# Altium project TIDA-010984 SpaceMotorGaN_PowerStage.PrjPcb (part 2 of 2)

## Sheet TIDA-010984 PowerSupply.SchDoc
size 431 x 279 mm; Date: Not shown in title block; ApprovedBy: Not shown in title block; CheckedBy: Not shown in title block; Author: Not shown in title block; CompanyName: Not shown in title block; Engineer: Not shown in title block; Organization: Not shown in title block; Address1: Not shown in title block; Address2: Not shown in title block; Address3: Not shown in title block; Address4: Not shown in title block; DocumentNumber: 2; Revision: Use project parameter SCH_Rev; SheetNumber: 3; SheetTotal: 6; PageSetup: Record=PageOptions¦CenterHorizontal=True¦CenterVertical=True¦PrintScale=1.00¦XCorrection=1.00¦YCorrection=1.00¦PrintKind=0¦BorderSize=5000000¦LeftOffset=0¦BottomOffset=0¦Orientation=2¦PaperLength=1000¦PaperWidth=1000¦Scale=100¦PaperSource=15¦PrintQuality=600¦MediaType=1¦DitherType=10¦PaperKind=Letter¦PrintScaleMode=1
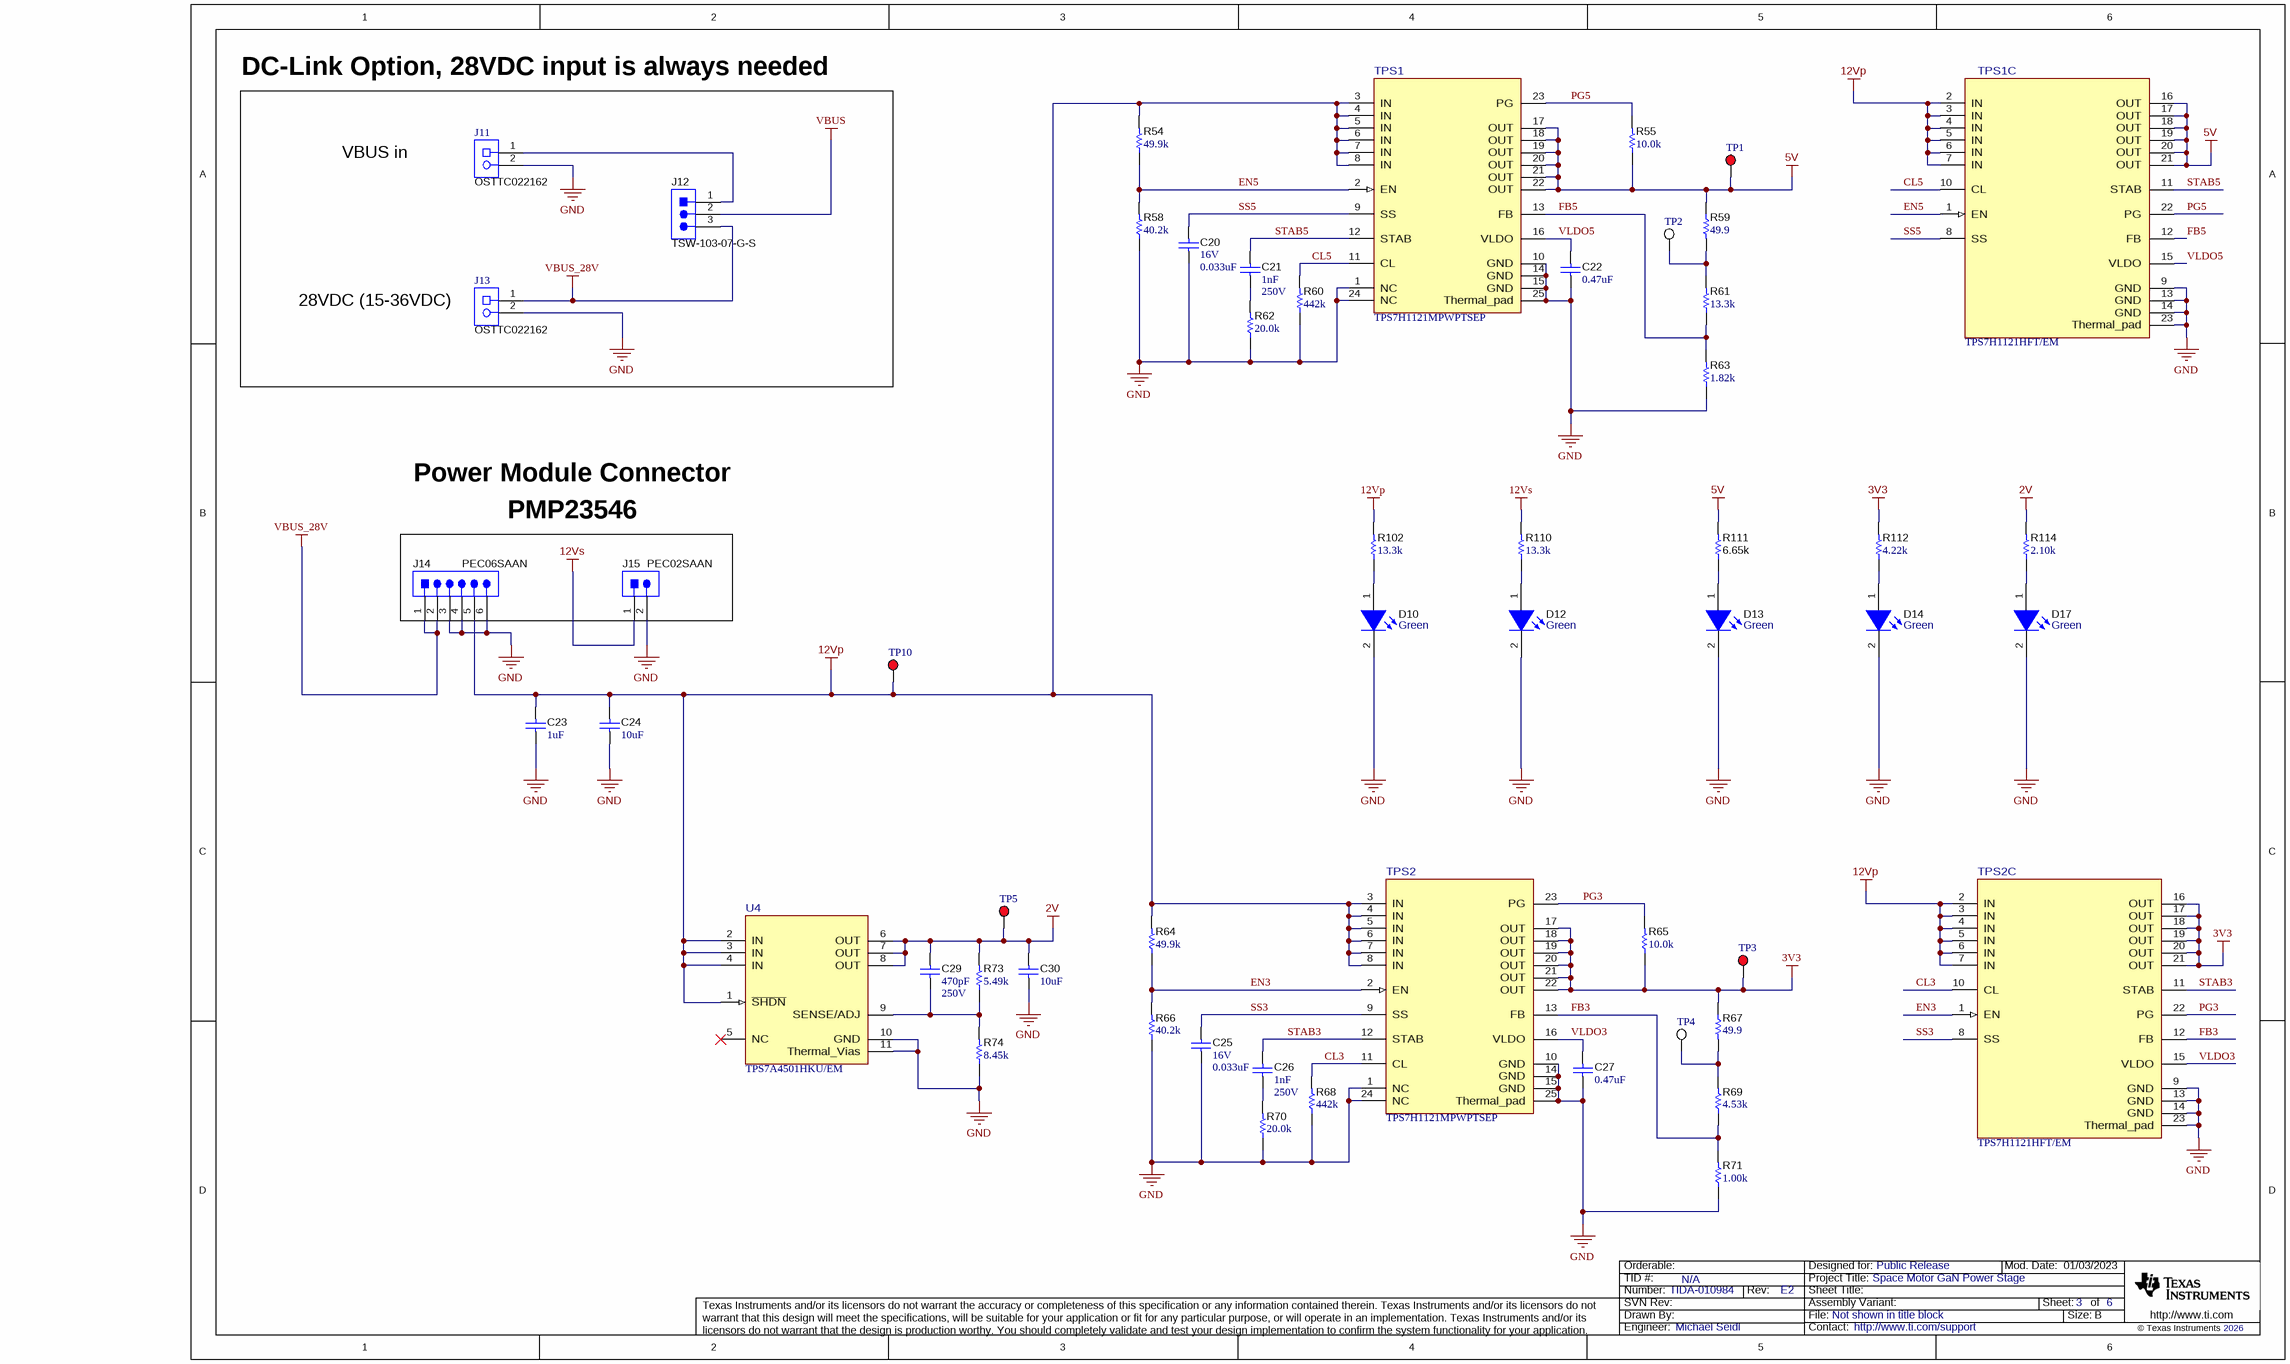
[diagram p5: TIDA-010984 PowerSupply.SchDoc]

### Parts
C20  VDC_V: 16V  ValueDisplayed: 0.033uF  [0603]  (hidden comment: GRM188R71C333KA01D)
C21  Cap_F: 1nF  VDC_V: 250V  [0603]  (hidden comment: GRM188R72E102KW07D)
C22  ValueDisplayed: 0.47uF  [0603]  (hidden comment: GRM188R71E474KA12D)
C23  ValueDisplayed: 1uF  [1210_150]  (hidden comment: 12103C105KAT2A)
C24  ValueDisplayed: 10uF  [1210_280]  (hidden comment: C1210C106K3RACTU)
C25  VDC_V: 16V  ValueDisplayed: 0.033uF  [0603]  (hidden comment: GRM188R71C333KA01D)
C26  Cap_F: 1nF  VDC_V: 250V  [0603]  (hidden comment: GRM188R72E102KW07D)
C27  ValueDisplayed: 0.47uF  [0603]  (hidden comment: GRM188R71E474KA12D)
C29  Cap_F: 470pF  VDC_V: 250V  [0603]  (hidden comment: GRM188R72E471KW07D)
C30  ValueDisplayed: 10uF  [1210_280]  (hidden comment: C1210C106K3RACTU)
D10  value Green  [APT2012_Green]  (hidden comment: APT2012LZGCK)
D12  value Green  [APT2012_Green]  (hidden comment: APT2012LZGCK)
D13  value Green  [APT2012_Green]  (hidden comment: APT2012LZGCK)
D14  value Green  [APT2012_Green]  (hidden comment: APT2012LZGCK)
D17  value Green  [APT2012_Green]  (hidden comment: APT2012LZGCK)
J11  OSTTC022162  [On-Shore_OSTTC022162]
J12  TSW-103-07-G-S  [TSW-103-07-G-S]
J13  OSTTC022162  [On-Shore_OSTTC022162]
J14  PEC06SAAN  [Sullins_PEC06SAAN]
J15  PEC02SAAN  [CONN_PEC02SAAN]
R54  ValueDisplayed: 49.9k  [0603]  (hidden comment: CRCW060349K9FKEA)
R55  ValueDisplayed: 10.0k  [0603]  (hidden comment: RC0603FR-0710KL)
R58  ValueDisplayed: 40.2k  [0603]  (hidden comment: CRCW060340K2FKEA)
R59  ValueDisplayed: 49.9  [0603]  (hidden comment: CRCW060349R9FKEA)
R60  ValueDisplayed: 442k  [0603]  (hidden comment: CRCW0603442KFKEA)
R61  ValueDisplayed: 13.3k  [0603]  (hidden comment: CRCW060313K3FKEA)
R62  ValueDisplayed: 20.0k  [0603]  (hidden comment: CRCW060320K0FKEA)
R63  ValueDisplayed: 1.82k  [0603]  (hidden comment: CRCW06031K82FKEA)
R64  ValueDisplayed: 49.9k  [0603]  (hidden comment: CRCW060349K9FKEA)
R65  ValueDisplayed: 10.0k  [0603]  (hidden comment: RC0603FR-0710KL)
R66  ValueDisplayed: 40.2k  [0603]  (hidden comment: CRCW060340K2FKEA)
R67  ValueDisplayed: 49.9  [0603]  (hidden comment: CRCW060349R9FKEA)
R68  ValueDisplayed: 442k  [0603]  (hidden comment: CRCW0603442KFKEA)
R69  ValueDisplayed: 4.53k  [0603]  (hidden comment: CRCW06034K53FKEA)
R70  ValueDisplayed: 20.0k  [0603]  (hidden comment: CRCW060320K0FKEA)
R71  ValueDisplayed: 1.00k  [0603]  (hidden comment: CRCW06031K00FKEA)
R73  ValueDisplayed: 5.49k  [0603]  (hidden comment: CRCW06035K49FKEA)
R74  ValueDisplayed: 8.45k  [0603]  (hidden comment: CRCW06038K45FKEA)
R102  ValueDisplayed: 13.3k  [0603]  (hidden comment: CRCW060313K3FKEA)
R110  ValueDisplayed: 13.3k  [0603]  (hidden comment: CRCW060313K3FKEA)
R111  ValueDisplayed: 6.65k  [0603]  (hidden comment: RC0603FR-076K65L)
R112  ValueDisplayed: 4.22k  [0603]  (hidden comment: RC0603FR-074K22L)
R114  ValueDisplayed: 2.10k  [0603]  (hidden comment: RC0603FR-072K1L)
TP1  5010  [Keystone5010]  (value not drawn)
TP2  5012  [Keystone5012]  (value not drawn)
TP3  5010  [Keystone5010]  (value not drawn)
TP4  5012  [Keystone5012]  (value not drawn)
TP5  5010  [Keystone5010]  (value not drawn)
TP10  5010  [Keystone5010]  (value not drawn)
TPS1  TPS7H1121MPWPTSEP  [PWP0024R-MFG]
TPS1C  TPS7H1121HFT/EM  [HFT0022A-C01-MFG]
TPS2  TPS7H1121MPWPTSEP  [PWP0024R-MFG]
TPS2C  TPS7H1121HFT/EM  [HFT0022A-C01-MFG]
U4  TPS7A4501HKU/EM  [HKU0010A-IPC_B]

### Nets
2V: C29.1 C30.1 R73.2 R114.2 TP5.1 U4.6(OUT) U4.7(OUT) U4.8(OUT)
3V3: R65.1 R67.1 R112.2 TP3.1 TPS2.17(OUT) TPS2.18(OUT) TPS2.19(OUT) TPS2.20(OUT) TPS2.21(OUT) TPS2.22(OUT) TPS2C.16(OUT) TPS2C.17(OUT) TPS2C.18(OUT) TPS2C.19(OUT) TPS2C.20(OUT) TPS2C.21(OUT)
5V: R55.1 R59.1 R111.2 TP1.1 TPS1.17(OUT) TPS1.18(OUT) TPS1.19(OUT) TPS1.20(OUT) TPS1.21(OUT) TPS1.22(OUT) TPS1C.16(OUT) TPS1C.17(OUT) TPS1C.18(OUT) TPS1C.19(OUT) TPS1C.20(OUT) TPS1C.21(OUT)
12Vp: C23.1 C24.1 J14.5 R54.2 R64.2 R102.2 TP10.1 TPS1.3(IN) TPS1.4(IN) TPS1.5(IN) TPS1.6(IN) TPS1.7(IN) TPS1.8(IN) TPS1C.2(IN) TPS1C.3(IN) TPS1C.4(IN) TPS1C.5(IN) TPS1C.6(IN) TPS1C.7(IN) TPS2.3(IN) TPS2.4(IN) TPS2.5(IN) TPS2.6(IN) TPS2.7(IN) TPS2.8(IN) TPS2C.2(IN) TPS2C.3(IN) TPS2C.4(IN) TPS2C.5(IN) TPS2C.6(IN) TPS2C.7(IN) U4.1(~{SHDN}) U4.2(IN) U4.3(IN) U4.4(IN)
12Vs: J15.1 R110.2
GND: C20.2 C22.2 C23.2 C24.2 C25.2 C27.2 C30.2 D10.2(K) D12.2(K) D13.2(K) D14.2(K) D17.2(K) J11.2 J13.2 J14.3 J14.4 J14.6 J15.2 R58.1 R60.1 R62.1 R63.1 R66.1 R68.1 R70.1 R71.1 R74.1 TPS1.1(NC) TPS1.10(GND) TPS1.14(GND) TPS1.15(GND) TPS1.24(NC) TPS1.25(Thermal_pad) TPS1C.9(GND) TPS1C.13(GND) TPS1C.14(GND) TPS1C.23(Thermal_pad) TPS2.1(NC) TPS2.10(GND) TPS2.14(GND) TPS2.15(GND) TPS2.24(NC) TPS2.25(Thermal_pad) TPS2C.9(GND) TPS2C.13(GND) TPS2C.14(GND) TPS2C.23(Thermal_pad) U4.10(GND) U4.11(Thermal_Vias)
VBUS: J12.2
VBUS_28V: J12.3 J13.1 J14.1 J14.2
CL3: R68.2 TPS2.11(CL) TPS2C.10(CL)
CL5: R60.2 TPS1.11(CL) TPS1C.10(CL)
EN3: R64.1 R66.2 TPS2.2(EN) TPS2C.1(EN)
EN5: R54.1 R58.2 TPS1.2(EN) TPS1C.1(EN)
FB3: R69.1 R71.2 TPS2.13(FB) TPS2C.12(FB)
FB5: R61.1 R63.2 TPS1.13(FB) TPS1C.12(FB)
PG3: R65.2 TPS2.23(PG) TPS2C.22(PG)
PG5: R55.2 TPS1.23(PG) TPS1C.22(PG)
SS3: C25.1 TPS2.9(SS) TPS2C.8(SS)
SS5: C20.1 TPS1.9(SS) TPS1C.8(SS)
STAB3: C26.1 TPS2.12(STAB) TPS2C.11(STAB)
STAB5: C21.1 TPS1.12(STAB) TPS1C.11(STAB)
VLDO3: C27.1 TPS2.16(VLDO) TPS2C.15(VLDO)
VLDO5: C22.1 TPS1.16(VLDO) TPS1C.15(VLDO)
NetC21_2: C21.2 R62.2
NetC26_2: C26.2 R70.2
NetC29_2: C29.2 R73.1 R74.2 U4.9(SENSE/ADJ)
NetD10_1: D10.1(A) R102.1
NetD12_1: D12.1(A) R110.1
NetD13_1: D13.1(A) R111.1
NetD14_1: D14.1(A) R112.1
NetD17_1: D17.1(A) R114.1
NetJ11_1: J11.1 J12.1
NetR59_2: R59.2 R61.2 TP2.1
NetR67_2: R67.2 R69.2 TP4.1

Not connected (* = marked no-connect by the designer): U4 5(NC)*

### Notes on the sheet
- DC-Link Option, 28VDC input is always needed
- VBUS in
- 28VDC (15-36VDC)
- Power Module Connector
- PMP23546

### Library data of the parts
C20 C25 = CMP-0007392-5: CAP, CERM, 0.033 uF, 16 V, +/- 10%, X7R, 0603; Manufacturer: MuRata; TaMin_C: -55°C; Polarized: N; SizeAreaWB_mm2: 4.68; Value1: Unknown; U/M: EA; TaMax_C: 125°C; SizeZ_mm: 1; SizeX_mm: 1.6; SizeY_mm: 0.8; SizeArea_mm2: 1.28; Cap_F: 33nF; AEC Category: Q200
C21 C26 = CMP-0007490-4: CAP, CERM, 1000 pF, 250 V, +/- 10%, X7R, 0603; Manufacturer: MuRata; TaMin_C: -55°C; Polarized: N; SizeAreaWB_mm2: 4.68; Value1: Unknown; U/M: EA; Value: 1000pF; TaMax_C: 125°C; SizeZ_mm: 1; SizeX_mm: 1.6; SizeY_mm: 0.8; SizeArea_mm2: 1.28; AEC Category: Q200
C22 C27 = CMP-0007424-4: CAP, CERM, 0.47 uF, 25 V, +/- 10%, X7R, 0603; Manufacturer: MuRata; TaMin_C: -55°C; Polarized: N; SizeAreaWB_mm2: 4.68; Value1: Unknown; U/M: EA; Value: 0.47uF; TaMax_C: 125°C; SizeZ_mm: 1; SizeX_mm: 1.6; SizeY_mm: 0.8; Value2: 25V; SizeArea_mm2: 1.28; Cap_F: 470nF; AEC Category: Q200
C23 = CMP-0009061-1: CAP, CERM, 1 uF, 25 V, +/- 10%, X7R, 1210; Manufacturer: AVX; TaMin_C: -55°C; Polarized: N; SizeAreaWB_mm2: 14.7; Value1: Unknown; U/M: EA; Value: 1uF; TaMax_C: 125°C; SizeZ_mm: 1.5; SizeX_mm: 3.2; SizeY_mm: 2.5; Cap_Case: 1210; Value2: 25V; SizeArea_mm2: 8; Cap_F: 1µF; AEC Category: Q200
C24 C30 = CMP-0009078-1: CAP, CERM, 10 uF, 25 V, +/- 10%, X7R, 1210; Manufacturer: Kemet; TaMin_C: -55°C; Polarized: N; SizeAreaWB_mm2: 14.7; Value1: Unknown; U/M: EA; Value: 10uF; TaMax_C: 125°C; SizeZ_mm: 2.8; SizeX_mm: 3.2; SizeY_mm: 2.5; Cap_Case: 1210; Value2: 25V; SizeArea_mm2: 8; Cap_F: 10µF; AEC Category: Q200
C29 = CMP-0007495-4: CAP, CERM, 470 pF, 250 V, +/- 10%, X7R, 0603; Manufacturer: MuRata; TaMin_C: -55°C; Polarized: N; SizeAreaWB_mm2: 4.68; Value1: Unknown; U/M: EA; Value: 470pF; TaMax_C: 125°C; SizeZ_mm: 1; SizeX_mm: 1.6; SizeY_mm: 0.8; SizeArea_mm2: 1.28; AEC Category: Q200
D10 D12-D14 D17 = CMP-0002953-3: LED, Green, SMD; Manufacturer: Kingbright; Vr_V: 5V; Value2: 2.65V; Ir_A: 50µA; Angle: 120; Tjmax_C: 85°C; Type: InGaN; Power_TotalModule: 75mW; Io_A: 2mA; Value1: 0.075W
J11 J13 = CMP-0075044-1: Terminal Block, 2-pole, 200mil, TH; Manufacturer: On-Shore Technology; CNHeader: False; CT: True; Green_Lifecycle: Not Set; Green_REACh: Incomplete
J12 = CMP-0075407-2: Header, 100mil, 3x1, Gold, TH; Manufacturer: Samtec; Pitch_mm: 2.54; Cert_VDE: N; Gender: Male; Cert_CSA: Y; Voltage_V: 550V; Green_REACh: Passed; Current_A: 6.3A; Green_Lifecycle: Active; Row_Count: 1
J14 = CMP-0054567-1: Header, 100mil, 6x1, Tin, TH; Manufacturer: Sullins Connector Solutions; CNHeader: TRUE; Green_Lifecycle: Not Set; Green_REACh: Incomplete; CT: FALSE
J15 = CMP-0002337-1: Header, 100mil, 2x1, Tin, TH; Manufacturer: Sullins Connector Solutions; Pitch_mm: 2.54; Gender: Male; Shrouded: N; Row_Count: 1; Current_A: 3A; Voltage_V: 1.8kV; Cert_UL: Y; CNHeader: TRUE; CT: FALSE; Green_Lifecycle: Not Set; Green_REACh: Incomplete
R54 R64 = CMP-0022447-4: RES, 49.9 k, 1%, 0.1 W, AEC-Q200 Grade 0, 0603; Manufacturer: Vishay-Dale; Power_W: 100mW; TempCo: 100 ppm/C; Value_Code: 49k9; Value: 49.9k; EIA_Code: E96; SizeX_mm: 1.6; SizeY_mm: 0.8; SizeZ_mm: 1; Value2: 0.1W; SizeArea_mm2: 1.28; AEC Qualified: Y; VDC_V: 75V; AEC Category: Q200; AEC Grade: 0
R55 R65 = CMP-0022746-5: RES, 10.0 k, 1%, 0.1 W, 0603; Manufacturer: Yageo; Power_W: 100mW; TempCo: 100 ppm/C; Value_Code: 10k0; Value: 10.0k; EIA_Code: E96; Res_ohm: 10k; SizeX_mm: 1.6; SizeY_mm: 0.8; SizeZ_mm: 1; Value2: 0.1W; SizeArea_mm2: 1.28; AEC Qualified: N; VDC_V: 75V; AEC Category: Q200; SizeAreaWB_mm2: 4.68
R58 R66 = CMP-0022410-4: RES, 40.2 k, 1%, 0.1 W, AEC-Q200 Grade 0, 0603; Manufacturer: Vishay-Dale; Power_W: 100mW; TempCo: 100 ppm/C; Value_Code: 40k2; Value: 40.2k; EIA_Code: E96; SizeX_mm: 1.6; SizeY_mm: 0.8; SizeZ_mm: 1; Value2: 0.1W; SizeArea_mm2: 1.28; AEC Qualified: Y; VDC_V: 75V; AEC Category: Q200; AEC Grade: 0
R59 R67 = CMP-0022448-4: RES, 49.9, 1%, 0.1 W, AEC-Q200 Grade 0, 0603; Manufacturer: Vishay-Dale; Power_W: 100mW; SizeZ_mm: 1; SizeArea_mm2: 1.28; Value2: 0.1W; Value_Code: 49R9; Value: 49.9; AEC Qualified: Y; AEC Category: Q200; AEC Grade: 0; SizeX_mm: 1.6; TempCo: 100 ppm/C; EIA_Code: E96; VDC_V: 75V; SizeY_mm: 0.8
R60 R68 = CMP-0022424-4: RES, 442 k, 1%, 0.1 W, AEC-Q200 Grade 0, 0603; Manufacturer: Vishay-Dale; Power_W: 100mW; TempCo: 100 ppm/C; Value: 442k; EIA_Code: E96; SizeX_mm: 1.6; SizeY_mm: 0.8; SizeZ_mm: 1; Value2: 0.1W; SizeArea_mm2: 1.28; AEC Qualified: Y; VDC_V: 75V; AEC Category: Q200; AEC Grade: 0
R61 R102 R110 = CMP-0022043-4: RES, 13.3 k, 1%, 0.1 W, AEC-Q200 Grade 0, 0603; Manufacturer: Vishay-Dale; Power_W: 100mW; TempCo: 100 ppm/C; Value_Code: 13k3; Value: 13.3k; EIA_Code: E96; SizeX_mm: 1.6; SizeY_mm: 0.8; SizeZ_mm: 1; Value2: 0.1W; SizeArea_mm2: 1.28; AEC Qualified: Y; VDC_V: 75V; AEC Category: Q200; AEC Grade: 0
R62 R70 = CMP-0022204-4: RES, 20.0 k, 1%, 0.1 W, AEC-Q200 Grade 0, 0603; Manufacturer: Vishay-Dale; Power_W: 100mW; TempCo: 100 ppm/C; Value_Code: 20k0; Value: 20.0k; EIA_Code: E96; Res_ohm: 20k; SizeX_mm: 1.6; SizeY_mm: 0.8; SizeZ_mm: 1; Value2: 0.1W; SizeArea_mm2: 1.28; AEC Qualified: Y; VDC_V: 75V; AEC Category: Q200; AEC Grade: 0
R63 = CMP-0022134-4: RES, 1.82 k, 1%, 0.1 W, AEC-Q200 Grade 0, 0603; Manufacturer: Vishay-Dale; Power_W: 100mW; TempCo: 100 ppm/C; Value_Code: 1k82; Value: 1.82k; EIA_Code: E96; SizeX_mm: 1.6; SizeY_mm: 0.8; SizeZ_mm: 1; Value2: 0.1W; SizeArea_mm2: 1.28; AEC Qualified: Y; VDC_V: 75V; AEC Category: Q200; AEC Grade: 0
R69 = CMP-0022454-4: RES, 4.53 k, 1%, 0.1 W, AEC-Q200 Grade 0, 0603; Manufacturer: Vishay-Dale; Power_W: 100mW; TempCo: 100 ppm/C; Value_Code: 4k53; Value: 4.53k; EIA_Code: E96; SizeX_mm: 1.6; SizeY_mm: 0.8; SizeZ_mm: 1; Value2: 0.1W; SizeArea_mm2: 1.28; AEC Qualified: Y; VDC_V: 75V; AEC Category: Q200; AEC Grade: 0
R71 = CMP-0022109-5: RES, 1.00 k, 1%, 0.1 W, AEC-Q200 Grade 0, 0603; Manufacturer: Vishay-Dale; Power_W: 100mW; TempCo: 100 ppm/C; Value_Code: 1k00; Value: 1.00k; EIA_Code: E96; Res_ohm: 1k; SizeX_mm: 1.6; SizeY_mm: 0.8; SizeZ_mm: 1; Value2: 0.1W; SizeArea_mm2: 1.28; AEC Qualified: Y; VDC_V: 75V; AEC Category: Q200; AEC Grade: 0
R73 = CMP-0022512-4: RES, 5.49 k, 1%, 0.1 W, AEC-Q200 Grade 0, 0603; Manufacturer: Vishay-Dale; Power_W: 100mW; TempCo: 100 ppm/C; Value_Code: 5k49; Value: 5.49k; EIA_Code: E96; SizeX_mm: 1.6; SizeY_mm: 0.8; SizeZ_mm: 1; Value2: 0.1W; SizeArea_mm2: 1.28; AEC Qualified: Y; VDC_V: 75V; AEC Category: Q200; AEC Grade: 0
R74 = CMP-0022636-4: RES, 8.45 k, 1%, 0.1 W, AEC-Q200 Grade 0, 0603; Manufacturer: Vishay-Dale; Power_W: 100mW; TempCo: 100 ppm/C; Value_Code: 8k45; Value: 8.45k; EIA_Code: E96; SizeX_mm: 1.6; SizeY_mm: 0.8; SizeZ_mm: 1; Value2: 0.1W; SizeArea_mm2: 1.28; AEC Qualified: Y; VDC_V: 75V; AEC Category: Q200; AEC Grade: 0
R111 = CMP-0023251-5: RES, 6.65 k, 1%, 0.1 W, 0603; Manufacturer: Yageo; Power_W: 100mW; TempCo: 100 ppm/C; Value_Code: 6k65; Value: 6.65k; EIA_Code: E96; SizeX_mm: 1.6; SizeY_mm: 0.8; SizeZ_mm: 1; Value2: 0.1W; SizeArea_mm2: 1.28; AEC Qualified: N; VDC_V: 75V; AEC Category: Q200; SizeAreaWB_mm2: 4.68
R112 = CMP-0023146-5: RES, 4.22 k, 1%, 0.1 W, 0603; Manufacturer: Yageo; Power_W: 100mW; TempCo: 100 ppm/C; Value_Code: 4k22; Value: 4.22k; EIA_Code: E96; SizeX_mm: 1.6; SizeY_mm: 0.8; SizeZ_mm: 1; Value2: 0.1W; SizeArea_mm2: 1.28; AEC Qualified: N; VDC_V: 75V; AEC Category: Q200; SizeAreaWB_mm2: 4.68
R114 = CMP-0022983-5: RES, 2.10 k, 1%, 0.1 W, 0603; Manufacturer: Yageo; Power_W: 100mW; TempCo: 100 ppm/C; Value_Code: 2k10; Value: 2.10k; EIA_Code: E96; Res_ohm: 2.1k; SizeX_mm: 1.6; SizeY_mm: 0.8; SizeZ_mm: 1; Value2: 0.1W; SizeArea_mm2: 1.28; AEC Qualified: N; VDC_V: 75V; AEC Category: Q200; SizeAreaWB_mm2: 4.68
TP1 TP3 TP5 TP10 = CMP-0055147-2: Test Point, Multipurpose, Red, TH; Manufacturer: Keystone Electronics; CNHeader: FALSE; Green_Lifecycle: Active; Green_REACh: Passed; ContactFinish: Silver; CT: TRUE
TP2 TP4 = CMP-0055149-2: Test Point, Multipurpose, White, TH; Manufacturer: Keystone Electronics; CNHeader: FALSE; Green_Lifecycle: Active; Green_REACh: Passed; ContactFinish: Silver; CT: TRUE
TPS1 TPS2 = CMP-0122232-1: 2.25 V to 14-V Input, 2-A, Radiation Hardened LDO Regulator; Manufacturer: Texas Instruments; SizeZ_mm: 1.2mm; AEC Qualified: No; Accuracy Percentage: 1.5%; Dropout Voltage: 1000mV; Max Supply Voltage: 14V; Min Supply Voltage: 2.25V; Nominal Supply Current: 8-10mA; Number Of Outputs: 1; Output Type: AdjustableProgrammable; Output Voltage: 0.6-13.9V; Standoff Height: 0.05mm; TJmax_C: +125°C
TPS1C TPS2C = CMP-0032523-3: 2.25 V to 14-V Input, 2-A, Radiation Hardened LDO Regulator; Manufacturer: Texas Instruments; SizeZ_mm: 2.428mm; AEC Qualified: No; Accuracy Percentage: 1.1%; Dropout Voltage: 1000mV; Max Supply Voltage: 14V; Min Supply Voltage: 2.25V; Nominal Supply Current: 10mA; Number Of Outputs: 1; Output Type: AdjustableProgrammable; Output Voltage: 0.6-13.9V; Standoff Height: 0.555mm; TJmax_C: +125°C; AEC Category: Q200; CompType: IC
U4 = CMP-0097443-1: LDO Regulator Pos 1.21V to 20V 0.75A 10-Pin CFP Tube; Manufacturer: Texas Instruments; Nominal Supply Current: 1-28mA; Output Type: AdjustableProgrammable; Dropout Voltage: 0.2V; Standoff Height: 0mm; SizeZ_mm: 2.62mm; TJmax_C: +125°C; Number Of Outputs: 1; AEC Qualified: No; Min Supply Voltage: 2.9V; Output Voltage: 1.21-20V; Accuracy Percentage: 1.15%

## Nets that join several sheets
2V: TIDA-010984 TempSensing (C57.2 U8.12), TIDA-010984 PowerSupply (8 pins)
3V3: PA (5 pins), PB (5 pins), PC (5 pins), PE (5 pins), PD (5 pins), PF (5 pins), TIDA-010984 Interface (20 pins), TIDA-010984 TempSensing (R96.2 R97.2 R98.2 R99.2), TIDA-010984 PowerSupply (16 pins)
5V: TIDA-010984 Interface (R2.1 R30.1), TIDA-010984 PowerSupply (16 pins)
12Vs: PA (C44_PA.2 R78_PA.2 TP7_PA.1 U6_PA.13), PB (C44_PB.2 R78_PB.2 TP7_PB.1 U6_PB.13), PC (C44_PC.2 R78_PC.2 TP7_PC.1 U6_PC.13), PE (C44_PE.2 R78_PE.2 TP7_PE.1 U6_PE.13), PD (C44_PD.2 R78_PD.2 TP7_PD.1 U6_PD.13), PF (C44_PF.2 R78_PF.2 TP7_PF.1 U6_PF.13), TIDA-010984 PowerSupply (J15.1 R110.2)
D-: PA (Q1_PA.2), PB (Q1_PB.2), PC (Q1_PC.2), PE (Q1_PE.2), PD (Q1_PD.2), PF (Q1_PF.2), TIDA-010984 TempSensing (10 pins)
GND: PA (54 pins), PB (54 pins), PC (54 pins), PE (54 pins), PD (54 pins), PF (54 pins), TIDA-010984 Interface (60 pins), TIDA-010984 TempSensing (C57.1 R100.2 U8.6), TIDA-010984 PowerSupply (49 pins)
VBUS: PA (7 pins), PB (7 pins), PC (7 pins), PE (7 pins), PD (7 pins), PF (7 pins), TIDA-010984 Interface (R56.2), TIDA-010984 PowerSupply (J12.2)
CS: PA (J17_PA.2), TIDA-010984 Interface (R7.1)
CS: PB (J17_PB.2), TIDA-010984 Interface (R10.1)
CS: PC (J17_PC.2), TIDA-010984 Interface (R11.1)
CS: PE (J17_PE.2), TIDA-010984 Interface (R37.1)
CS: PD (J17_PD.2), TIDA-010984 Interface (R34.1)
CS: PF (J17_PF.2), TIDA-010984 Interface (R38.1)
D+: PA (Q1_PA.1 Q1_PA.3), TIDA-010984 TempSensing (C34.2 R104.1)
D+: PB (Q1_PB.1 Q1_PB.3), TIDA-010984 TempSensing (C32.2 R101.1)
D+: PC (Q1_PC.1 Q1_PC.3), TIDA-010984 TempSensing (C33.2 R103.1)
D+: PE (Q1_PE.1 Q1_PE.3), TIDA-010984 TempSensing (C58.2 R106.1)
D+: PD (Q1_PD.1 Q1_PD.3), TIDA-010984 TempSensing (C60.2 R108.1)
D+: PF (Q1_PF.1 Q1_PF.3), TIDA-010984 TempSensing (C45.2 R105.1)
Phase: TIDA-010984 SpaceMotorGaN_TOPLEVEL (J10.1), PD (R85_PD.2 R88_PD.2 R90_PD.1)
Phase: TIDA-010984 SpaceMotorGaN_TOPLEVEL (J10.2), PE (R85_PE.2 R88_PE.2 R90_PE.1)
Phase: TIDA-010984 SpaceMotorGaN_TOPLEVEL (J10.3), PF (R85_PF.2 R88_PF.2 R90_PF.1)
Phase: TIDA-010984 SpaceMotorGaN_TOPLEVEL (J9.1), PC (R85_PC.2 R88_PC.2 R90_PC.1)
Phase: TIDA-010984 SpaceMotorGaN_TOPLEVEL (J9.2), PB (R85_PB.2 R88_PB.2 R90_PB.1)
Phase: TIDA-010984 SpaceMotorGaN_TOPLEVEL (J9.3), PA (R85_PA.2 R88_PA.2 R90_PA.1)
PWM_AH: PA (R82_PA.2), TIDA-010984 Interface (R20.2 U1.21)
PWM_AL: PA (R83_PA.2), TIDA-010984 Interface (R21.2 U1.20)
PWM_BH: PB (R82_PB.2), TIDA-010984 Interface (R22.2 U1.19)
PWM_BL: PB (R83_PB.2), TIDA-010984 Interface (R23.2 U1.18)
PWM_CH: PC (R82_PC.2), TIDA-010984 Interface (R24.2 U1.17)
PWM_CL: PC (R83_PC.2), TIDA-010984 Interface (R25.2 U1.16)
PWM_DH: PD (R82_PD.2), TIDA-010984 Interface (R45.2 U2.21)
PWM_DL: PD (R83_PD.2), TIDA-010984 Interface (R46.2 U2.20)
PWM_EH: PE (R82_PE.2), TIDA-010984 Interface (R47.2 U2.19)
PWM_EL: PE (R83_PE.2), TIDA-010984 Interface (R48.2 U2.18)
PWM_FH: PF (R82_PF.2), TIDA-010984 Interface (R49.2 U2.17)
PWM_FL: PF (R83_PF.2), TIDA-010984 Interface (R50.2 U2.16)
SCL: TIDA-010984 Interface (R115.1 R117.1), TIDA-010984 TempSensing (R96.1 U8.11)
SDA: TIDA-010984 Interface (R116.1 R118.1), TIDA-010984 TempSensing (R97.1 U8.10)
THERM: TIDA-010984 Interface (J4.4 J8.4), TIDA-010984 TempSensing (R98.1 U8.8)
THERM1: TIDA-010984 Interface (J4.3 J8.3), TIDA-010984 TempSensing (R99.1 U8.9)
V_PH: PA (C53_PA.1 R88_PA.1 R92_PA.2), TIDA-010984 Interface (R4.1)
V_PH: PB (C53_PB.1 R88_PB.1 R92_PB.2), TIDA-010984 Interface (R5.1)
V_PH: PC (C53_PC.1 R88_PC.1 R92_PC.2), TIDA-010984 Interface (R6.1)
V_PH: PE (C53_PE.1 R88_PE.1 R92_PE.2), TIDA-010984 Interface (R32.1)
V_PH: PD (C53_PD.1 R88_PD.1 R92_PD.2), TIDA-010984 Interface (R31.1)
V_PH: PF (C53_PF.1 R88_PF.1 R92_PF.2), TIDA-010984 Interface (R33.1)

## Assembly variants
001: not fitted C21 C26 C32 C33 C34 C37_PA C37_PB C37_PC C37_PD C37_PE C37_PF C41_PA C41_PB C41_PC C41_PD C41_PE C41_PF C42_PA C42_PB C42_PC C42_PD C42_PE C42_PF C45 C46_PA C46_PB C46_PC C46_PD C46_PE C46_PF C58 C59 C60 R1 R29 R62 R70 R80_PA R80_PB R80_PC R80_PD R80_PE R80_PF R84_PA R84_PB R84_PC R84_PD R84_PE R84_PF R87_PA R87_PB R87_PC R87_PD R87_PE R87_PF TPS7H1121 Ceramic TPS7H1121 Ceramic1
